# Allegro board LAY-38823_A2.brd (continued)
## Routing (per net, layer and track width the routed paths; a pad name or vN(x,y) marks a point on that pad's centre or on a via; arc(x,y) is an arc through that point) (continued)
VDD_ARM_0V9: length 27
  TOP w0.203: v2(14.96,14.43) 15.24,14.43 15.69,14.88 R191.2
  TOP w0.254: U1.W16 24.49,26.29 v1(24.45,26.25) ; v1(24.97,27.21) U1.V16
  L3_IN1 w0.104: v1(23.5,27.76) 22.01,27.76 20.65,26.39 19.53,26.39 18.92,25.78 18.92,18.39 v2(14.96,14.43)
  BOTTOM w0.254: v1(23.5,27.76) 23.49,27.75 v1(23.49,27.2) ; v1(23.49,27.2) 23.49,26.95 22.99,26.45 C251.1 ; v1(23.49,27.2) 23.64,27.06 C33.1 ; C33.1 24.46,27.06 24.61,27.21 v1(24.97,27.21) 24.94,27.18 C248.1 ; C33.1 24.45,26.82 v1(24.45,26.25) 24.33,26.37 C36.1 ; C35.1 23.38,28.5 v1(23.52,28.64) 23.67,28.49 C253.1
  vias: v1(14.73,17.65) v1(14.78,18.26) v1(15.52,18.26) v1(15.53,17.66) v1(16.17,18.27) v1(16.18,17.58)
VDD_PHY_1V2: length 64.1
  TOP w0.203: U8.1 6.31,13.34 5.88,13.78 v2(5.88,13.79) 5.77,13.89 5.64,13.89 4.47,15.06 3.53,15.06 TP31.1
  TOP w0.254: U1.J15 24.46,32.17 v1(24.47,32.17)
  L5_PWR_2 w0.381: v2(5.88,13.79) 5.93,13.84 25.44,13.84 30.28,18.68 30.28,21.49 31.75,22.96 31.75,30.51 30.27,31.99 30.27,35.22 27.68,37.81 v1(27.68,38.73)
  BOTTOM w0.254: C351.1 5.79,13.88 v2(5.88,13.79)
  BOTTOM w0.305: 25.95,32.51 25.57,32.13 C244.1 24.52,32.13 v1(24.47,32.17)
  BOTTOM w0.381: v1(27.68,38.73) 25.95,37 25.95,32.51
VDD_SNVS_0V8: length 75.8
  TOP w0.203: U8.2 6.09,12.94 5.77,13.26 5.56,13.26 v2(5.5,13.31) 4.15,14.67 TP29.1
  TOP w0.254: v1(27.48,30.73) 27.49,30.74 U1.K22 ; v2(35.01,42.77) R113.1
  L3_IN1 w0.254: v2(35.01,42.77) 35.01,40.84 35.71,40.14 36.83,40.14 38.78,38.19 38.78,37.13 36.7,35.05 36.7,32.7 35.03,31.03 30.29,31.03 29.9,31.42 28.06,31.42 27.48,30.85 v1(27.48,30.73)
  L5_PWR_2 w0.381: v2(5.5,13.31) 5.33,13.49 5.33,14.07 5.61,14.35 12.28,14.35 12.91,14.97 16.6,14.97 17.22,14.35 24.85,14.35 28.34,17.85 28.34,21.56 30.93,24.15 30.93,30.03 29.71,31.25 27.75,31.25 27.48,30.99 v1(27.48,30.73)
  BOTTOM w0.254: C9.1 27.82,31.23 27.48,30.9 v1(27.48,30.73) ; C337.1 5.84,13.31 5.59,13.31 5.58,13.31 v2(5.5,13.31)
VDD_SOC&DRAM&PU_0V9: length 45.6
  TOP w0.203: R194.2 18.95,14.86 v2(18.95,14.99)
  TOP w0.254: U1.R17 24.95,28.75 v1(24.95,29.23) ; U1.L10 21.49,30.26 v1(21.46,30.22) 21.49,30.19 U1.N10 U1.P9 U1.R10 21.49,28.26 v1(21.45,28.21) 21.49,28.17 U1.U10 ; U1.P12 22.03,29.21 v1(22.03,29.21) ; 21.99,29.24 v1(22.03,29.21) ; v1(22.03,29.21) 21.99,29.17 U1.R11 ; U1.U17 U1.U18 25.53,27.75 v1(25.53,28.2) 25.53,28.67 U1.R18 25.52,28.74 v1(25.52,29.22) ; U1.U10 U1.W10 ; U1.U10 U1.U11 ; U1.L17 U1.L18 25.5,30.7 v1(25.5,30.21) 25.49,30.21 U1.N18 25.52,29.68 v1(25.52,29.22) ; v1(24.95,29.23) 24.95,29.67 U1.N17 ; v1(24.95,29.23) 24.96,29.22 v1(25.52,29.22) ; v1(24.95,29.23) 24.51,29.23 U1.P16 U1.N15 U1.M15 U1.L15 U1.K15
  L3_IN1 w0.076: v1(22.03,27.21) 21.49,26.67 21.49,26.23 20.93,25.67 20,25.67 19.56,25.22
  L3_IN1 w0.104: v2(18.95,14.99) 19.2,15.24 19.2,24.87 19.56,25.22
  BOTTOM w0.203: C74.1 21.13,29.9 v1(21.46,30.22) ; C1.1 23.19,31.47 v1(23.42,31.24) ; C61.1 21.08,28.02 21.27,28.21 v1(21.45,28.21)
  BOTTOM w0.254: v1(25.5,30.21) 25.77,30.49 C235.1 25.77,30.94 v1(25.54,31.17) 25.54,31.17 v1(25.04,31.17) 25.04,31.5 24.83,31.71 C256.1 ; v1(25.5,30.21) 25.5,29.72 C254.1 25.49,29.25 v1(25.52,29.22) ; v1(25.5,30.21) 25.82,30.21 C234.2 ; v1(25.52,29.22) 24.96,29.22 v1(24.95,29.23) 24.68,29.23 C247.1 24.15,29.76 v1(23.5,29.76) 23.42,29.67 C16.1 ; v1(25.52,29.22) 25.5,29.19 C255.1 25.5,28.24 v1(25.53,28.2) 25.53,27.77 C15.1 ; v1(23.49,30.69) 23.48,30.7 23.48,31.19 v1(23.42,31.24) 23.01,31.24 22.9,31.14 C20.1 22.09,31.14 v1(22.03,31.2) ; v1(22.03,29.21) 22.29,28.95 C54.1 ; v1(21.46,30.22) 21.46,30.32 21.25,30.52 C78.1 ; C55.1 22.18,27.06 v1(22.03,27.21) 21.61,27.21 C48.1
  BOTTOM w0.305: v1(23.42,31.24) 23.65,31.46 C65.1
  vias: v2(18.24,11.2) v2(18.29,12.22) v2(19,12.22) v2(19,11.23)
VDDA_1V8: length 37.3
  TOP w0.203: U8.54 8.21,14.8 v2(7.63,15.38) 7.25,15.76 5.43,15.76 5.23,15.96 5.23,16.66 TP32.1
  TOP w0.254: U1.H13 23.42,32.21 v1(23.47,32.26) 23.49,32.28 23.92,32.28 U1.H15 ; U1.AA14 23.47,25.73 v1(23.47,26.24) 23.5,26.21 U1.Y15 ; U1.P19 U1.N19 U1.N20 26.51,29.69 v1(26.51,29.23) 26.49,29.21 U1.P19 ; U1.P19 U1.R19 ; v1(18.49,29.18) 18.97,29.18 U1.P5
  L3_IN1 w0.254: 22.7,28.77 18.87,28.77 18.54,29.11 18.54,29.13 v1(18.49,29.18)
  L3_IN1 w0.381: v2(7.63,15.38) 7.63,15.26 9.04,13.84 19.38,13.84 v2(20.45,14.91)
  BOTTOM w0.203: v1(18.49,29.18) 18.44,29.13 18.39,29.13 18.33,29.07 C267.1
  BOTTOM w0.254: 24.01,22.77 23.95,22.83 23.95,24.43 23.6,24.77 23.53,24.77 23.4,24.9 C99.1 23.4,25.51 23.47,25.58 v1(23.47,26.24) ; C104.1 26.8,28.94 v1(26.51,29.23) 26.13,28.86 C101.1 ; v1(23.47,32.26) 23.47,32.5 C100.1 ; C363.1 7.63,14.91 v2(7.63,15.38)
VIN_LDO_CAP: length 0.7
  BOTTOM w0.254: v2(53.43,34.59) 53.29,34.46 C122.1
VINT: length 1.7
  TOP w0.203: C274.2 5.1,12.52 5.43,12.19 6.02,12.19 6.07,12.14 U8.4
32K_CLKIN: length 1.8
  TOP w0.104: v2(54.64,32.86) 54.49,33.02 U9.24
  BOTTOM w0.104: R115.2 v2(54.64,32.86)
ANT_IN0: length 4.5
  TOP w0.279: U9.2 67.24,25.82 arc(67.56,25.75) 67.84,25.57 67.91,25.5 arc(68.04,25.3) 68.08,25.07 68.1,25.06 C456.1 68.1,24.12 C455.1
BOOT_MODE0: length 28.9
  TOP w0.076: U1.G26 29.75,32.96 30.37,32.96
  TOP w0.104: v1(34.77,32.67) 34.58,32.48 34.03,32.48 33.53,32.98 30.38,32.98
  TOP w0.114: 30.38,32.98 30.37,32.96
  BOTTOM w0.104: R47.1 34.77,32.36 v1(34.77,32.67) 34.77,33.37 37.48,36.08 37.48,47.94 36.27,49.15 34.82,49.15 34.39,48.72 33.25,48.72 32.87,49.11 J4.98
BOOT_MODE1: length 29.5
  TOP w0.104: 30.03,32.74 33.42,32.74 33.93,32.24 35.03,32.24 35.28,32.49 v1(35.28,33.32)
  TOP w0.114: 30.03,32.74 U1.G27
  BOTTOM w0.104: J4.100 33.27,49.14 33.45,48.95 34.25,48.95 34.75,49.46 36.35,49.46 37.74,48.06 37.74,35.79 v1(35.28,33.32) 35.28,32.17 R79.1
BOOT_MODE2: length 28.7
  TOP w0.104: v1(33.81,34.8) 32.76,35.84 31.42,35.84 30.29,34.71 U1.C27
  L3_IN1 w0.081: v1(26.06,47.71) 26.89,46.88 27.12,46.88 27.54,46.46 28.17,46.46 28.45,46.19 28.45,45.16 29.54,44.07 32.47,44.07 33.64,42.89 33.64,34.96 v1(33.81,34.8)
  BOTTOM w0.104: R78.1 32.6,31.85 33.63,32.88 33.63,33.96 33.81,34.14 v1(33.81,34.8) ; J4.60 25.27,48.82 25.32,48.77 25.32,48.29 25.9,47.71 v1(26.06,47.71)
BOOT_MODE3: length 29.1
  TOP w0.076: U1.D26 29.75,34.46 30.31,34.46 31.3,35.46 31.63,35.46
  TOP w0.104: v1(24.47,48.78) 24.9,49.21 30.7,49.21 v1(35,44.91) ; 31.63,35.46 32.01,35.46 32.11,35.36 v1(32.18,35.36)
  BOTTOM w0.104: R77.1 35.96,45.86 v1(35,44.91) 34.16,44.07 34.16,37.02 32.5,35.36 v1(32.18,35.36) ; J4.56 v1(24.47,48.78)
BT_CTS_RES: length 138.6
  TOP w0.104: U9.44 v2(63.72,24.74)
  L3_IN1 w0.081: v1(8.2,40.4) 8.04,40.56 5.6,40.56 1.88,36.84 1.88,35.38 1.18,34.68 1.18,20.18 1.76,19.6 1.76,5.48 5.49,1.74 19.95,1.74 21.62,3.41 37.56,3.41 39.37,5.22 39.37,8.97 48.06,17.67 48.06,21.42 49.59,22.95 50.67,22.95 51.77,24.06 59.27,24.06 60.47,25.26 63.19,25.26 63.71,24.74 v2(63.72,24.74)
  BOTTOM w0.104: v1(8.2,40.4) 8.68,40.87 9.55,40.87 10.52,41.84 21.45,41.84 25.27,38.02 R205.1
BT_RTS_RES: length 135.3
  TOP w0.104: v2(61.02,24.72) U9.41
  L3_IN1 w0.081: v1(8.97,40.49) 8.69,40.77 5.52,40.77 1.67,36.92 1.67,35.43 0.97,34.73 0.97,20.09 1.55,19.51 1.55,5.34 5.35,1.54 20.15,1.54 21.16,2.54 21.9,2.54 22.56,3.21 37.75,3.21 39.64,5.09 39.64,8.9 48.36,17.63 48.36,21.43 49.68,22.74 50.82,22.74 51.91,23.84 60.14,23.84 v2(61.02,24.72)
  BOTTOM w0.104: v1(8.97,40.49) 9.6,40.49 10.64,41.53 21.23,41.53 24.22,38.54 R208.1
BT_RXD_RES: length 136.4
  TOP w0.104: U9.43 v2(62.82,24.73)
  L3_IN1 w0.081: v2(62.82,24.73) 61.45,23.36 52.28,23.36 51.25,22.33 49.87,22.33 48.94,21.39 48.94,17.59 40.17,8.82 40.17,5.03 37.91,2.78 28.25,2.78 26.58,1.11 5.16,1.11 1.13,5.14 1.13,19.34 0.55,19.92 0.55,20.09 0.55,36.4 1.91,37.75 1.91,37.75 5.34,41.18 9.87,41.18 10.67,40.39 v1(10.95,40.39)
  BOTTOM w0.104: R206.1 22.1,38.76 20.08,40.77 11.33,40.77 v1(10.95,40.39)
BT_TXD_RES: length 136.1
  TOP w0.104: U9.42 v2(61.92,24.72)
  L3_IN1 w0.081: v2(61.92,24.72) 60.78,23.57 52.08,23.57 51.04,22.54 49.79,22.54 48.68,21.43 48.68,17.63 39.9,8.85 39.9,5.06 37.82,2.98 28.16,2.98 26.49,1.32 5.25,1.32 1.34,5.22 1.34,19.43 0.76,20.01 0.76,36.31 1.7,37.25 5.43,40.97 9.43,40.97 v1(10.09,40.31)
  BOTTOM w0.104: v1(10.09,40.31) 10.09,40.39 10.77,41.07 21.03,41.07 23.16,38.94 R207.1
BT_WAKE_DEV: length 51
  TOP w0.076: U1.U26 29.75,27.46 30.27,27.46
  TOP w0.104: 30.27,27.46 33.63,27.46 34.15,26.93 40.53,26.93 43.59,29.99 47.54,29.99 49.75,32.2 49.75,37.77 51.34,39.37 58.57,39.37 v2(59.39,38.55) ; U9.6 v2(63.89,29.42)
  BOTTOM w0.104: v2(63.89,29.42) 63.89,30.38 59.39,34.88 v2(59.39,38.55)
BT_WAKE_HOST: length 48.3
  TOP w0.076: 31.63,26.71 U1.W27
  TOP w0.104: U9.7 62.9,30.32 v2(62.83,30.39) ; v2(57.14,38.18) 56.65,38.67 52,38.67 51.12,37.79 51.12,32.08 47.37,28.34 43.9,28.34 41.8,26.24 33.87,26.24 33.39,26.71 31.63,26.71
  BOTTOM w0.104: v2(57.14,38.18) 57.14,36.07 v2(62.83,30.39)
CLK_32K_OUT: length 77.2
  TOP w0.104: U8.7 5.3,10.94 v2(5.21,10.85) ; v2(18.5,6.18) 18.78,6.18 19.96,7.37 23.85,7.37 24.41,7.92 28.07,7.92 30.66,5.33 30.66,4.95 30.83,4.77 30.83,4.49 31.46,3.86 35.96,3.86 38.22,6.12 38.22,16.78 v2(38.51,17.06) ; v2(38.15,40.62) 37.81,40.95 R100.1
  L3_IN1 w0.081: v2(5.21,10.85) 5.21,10.31 7.47,8.05 7.97,8.05 10.52,5.5 17.82,5.5 v2(18.5,6.18)
  BOTTOM w0.104: v2(38.51,17.06) 38.28,17.29 38.28,34.75 39.06,35.53 39.06,39.71 v2(38.15,40.62)
CLKIN1: length 27.6
  TOP w0.104: v1(32.27,48.57) 32.27,48.43 36.87,43.82 TP20.1 38.56,41.56 38.56,40.05 37.67,39.17 37.67,35.7 36.25,34.28 36.25,32.65 35.95,32.35 35.53,32.35 35.18,32 33.83,32 33.32,32.5 31.7,32.5 31.13,31.93
  TOP w0.114: U1.H27 30.04,32.16 30.26,32.16 30.49,31.93 31.13,31.93
  BOTTOM w0.104: v1(32.27,48.57) 32.27,48.92 32.07,49.12 J4.94
CLKIN2: length 28.2
  TOP w0.104: v1(32.84,48.57) 32.84,48.24 38.81,42.27 38.81,39.98 37.9,39.07 37.9,35.61 36.48,34.19 36.48,32.57 36.48,32.57 36.48,32.55 36.14,32.21 36.14,31.72 35.87,31.45 33.22,31.45 TP21.1 32.26,31.45 30.25,31.45
  TOP w0.114: U1.J27 30.25,31.45
  BOTTOM w0.104: v1(32.84,48.57) 32.84,48.67 32.47,49.04 J4.96
CLKOUT1: length 28
  TOP w0.076: 30.23,32.46 29.74,32.46 U1.H26
  TOP w0.114: 30.23,32.46 30.99,32.46 v1(31.06,32.38)
  L3_IN1 w0.081: v1(31.06,32.38) 31.66,32.98 33.72,32.98 34.61,33.86 34.61,34.9 34.29,35.22 34.29,45.34 33.12,46.51 31.14,46.51 30.74,46.92 28.01,46.92 27.66,47.26 27.33,47.26 26.46,48.13 26.46,48.46 v1(26.1,48.82)
  BOTTOM w0.104: J4.64 26.07,48.85 v1(26.1,48.82)
CLKOUT2: length 28.4
  TOP w0.076: U1.J26 29.75,31.96 30.18,31.96
  TOP w0.114: v1(31.86,32.12) 31.58,32.12 31.16,31.69 30.45,31.69 30.18,31.96
  L3_IN1 w0.081: v1(26.83,48.28) 26.83,48.18 27.51,47.5 27.81,47.5 28.15,47.17 30.79,47.17 31.23,46.72 33.2,46.72 34.55,45.38 34.55,35.49 34.82,35.22 34.82,33.78 33.81,32.77 32.51,32.77 v1(31.86,32.12)
  BOTTOM w0.104: J4.66 26.47,49.07 26.48,49.05 26.48,48.66 26.83,48.32 v1(26.83,48.28)
CSI_CKN: length 13.5
  TOP w0.076: v1(22.07,45.56) 21.78,45.56 21.45,45.23 21.45,43.68 24.51,40.62 24.51,35.73 U1.A16
  BOTTOM w0.076: J4.45 22.47,46.44 22.64,46.27 22.64,45.57 22.51,45.44 22.19,45.44 v1(22.07,45.56)
CSI_CKP: length 13.6
  TOP w0.076: U1.B16 24.74,35.46 24.74,40.71 23.46,42 21.68,43.78 21.68,44.64 22.06,45.02 v1(22.07,45.02)
  BOTTOM w0.076: v1(22.07,45.02) 22.26,45.21 22.61,45.21 22.87,45.47 J4.47
CSI_DN0: length 14.3
  TOP w0.076: U1.A14 23.51,35.73 23.51,39.57 18.83,44.25 18.83,45.2 19.2,45.56 v1(19.51,45.56)
  BOTTOM w0.076: v1(19.51,45.56) 19.51,45.48 19.63,45.35 19.85,45.35 20.17,45.68 20.17,46.33 20.07,46.43 J4.33
CSI_DN1: length 14
  TOP w0.076: v1(20.78,45.55) 20.44,45.55 20.15,45.26 20.15,43.99 24.01,40.14 24.01,35.73 U1.A15
  BOTTOM w0.076: J4.39 21.27,46.4 21.44,46.23 21.44,45.63 21.15,45.34 20.98,45.34 v1(20.78,45.55)
CSI_DN2: length 13.3
  TOP w0.076: v1(23.26,45.56) 22.99,45.56 22.64,45.21 22.64,43.43 25.01,41.06 25.01,35.73 U1.A17
  BOTTOM w0.076: v1(23.26,45.56) 23.49,45.34 23.73,45.34 23.81,45.41 23.81,46.34 23.67,46.48 J4.51
CSI_DN3: length 12.9
  TOP w0.076: v1(24.51,45.56) 24.23,45.56 23.89,45.22 23.89,43.29 25.52,41.66 25.52,35.73 U1.A18
  BOTTOM w0.076: J4.57 24.87,46.47 25,46.33 25,45.43 24.93,45.35 24.72,45.35 v1(24.51,45.56)
CSI_DP0: length 14.4
  TOP w0.076: v1(19.48,45.02) 19.46,45.02 19.06,44.62 19.06,44.34 23.74,39.66 23.74,35.46 U1.B14
  BOTTOM w0.076: v1(19.48,45.02) 19.59,45.12 19.94,45.12 20.41,45.59 20.41,46.37 20.47,46.43 J4.35
CSI_DP1: length 14
  TOP w0.076: v1(20.78,45.02) 20.38,44.62 20.38,44.09 24.24,40.23 24.24,35.46 U1.B15
  BOTTOM w0.076: J4.41 21.67,45.53 21.25,45.11 20.87,45.11 v1(20.78,45.02)
CSI_DP2: length 13.4
  TOP w0.076: v1(23.29,45.03) 22.87,44.61 22.87,43.52 25.24,41.15 25.24,35.46 U1.B17
  BOTTOM w0.076: v1(23.29,45.03) 23.37,45.11 23.83,45.11 24.04,45.32 24.04,46.23 24.07,46.26 J4.53
CSI_DP3: length 13
  TOP w0.076: v1(24.51,45.03) 24.51,45.01 24.12,44.62 24.12,43.39 25.75,41.76 25.75,35.46 U1.B18
  BOTTOM w0.076: v1(24.51,45.03) 24.61,45.12 25.02,45.12 25.23,45.33 25.23,46.21 25.27,46.25 J4.59
DRAM_CA0_A: length 19
  TOP w0.084: U1.J6 19.31,31.9 19.31,31.95 v1(19.1,32.16)
  TOP w0.089: v1(2.98,31.11) 2.95,31.11 U2.H2
  L3_IN1 w0.081: v1(19.1,32.16) 19.1,32.13 18.49,31.52 15.95,31.52 15.03,32.44 10.82,32.44 10.29,32.97 8.89,32.97 8.02,32.1 7.36,32.1 7.07,31.81 4.45,31.81 3.99,31.34 3.15,31.34 2.98,31.18 v1(2.98,31.11)
DRAM_CA1_A: length 20.5
  TOP w0.084: v1(19,30.76) 19.04,30.76 U1.K6
  TOP w0.089: v1(2.99,30.48) 2.94,30.48 U2.J2
  L3_IN1 w0.081: v1(19,30.76) 19,30.81 18.54,31.27 15.62,31.27 15.06,31.83 13.89,31.83 13.78,31.71 13.78,31.6 13.7,31.52 13.54,31.52 13.46,31.6 13.46,31.71 13.37,31.8 13.21,31.8 13.13,31.71 13.13,31.6 13.05,31.52 12.89,31.52 12.81,31.6 12.81,31.71 12.72,31.8 12.56,31.8 12.48,31.71 12.48,31.6 12.4,31.52 12.24,31.52 12.15,31.6 12.15,31.71 12.07,31.8 10.75,31.8 9.82,32.72 9.15,32.72 8.15,31.72 8.15,31.57 7.62,31.04 5.2,31.04 4.82,31.42 4.44,31.42 4.04,31.01 3.53,31.01 v1(2.99,30.48)
DRAM_CA2_A: length 16.6
  TOP w0.084: U2.H9 7.94,31.72 v1(7.8,31.72) ; U1.E4 18.49,34.15 v1(18.53,34.18)
  BOTTOM w0.104: v1(18.53,34.18) 18.48,34.18 17.22,32.92 17.22,32.23 16.58,31.6 14.68,31.6 14.43,31.85 14.43,32.38 14.32,32.49 13.61,32.49 13.51,32.38 13.51,31.88 13.43,31.8 13.04,31.8 12.94,31.9 12.94,32.34 12.83,32.45 12.62,32.45 12.52,32.34 12.52,31.9 12.42,31.8 12.21,31.8 12.1,31.9 12.1,32.34 12,32.45 10.88,32.45 10.51,32.82 9.22,32.82 8.13,31.72 v1(7.8,31.72)
DRAM_CA3_A: length 15.7
  TOP w0.084: v1(9.38,31.16) 9.31,31.16 U2.H10 ; v1(18.96,33.76) 18.99,33.79 U1.D5
  BOTTOM w0.104: v1(9.38,31.16) 9.65,31.16 9.75,31.06 9.75,30.15 10.13,29.77 12.01,29.77 12.11,29.87 12.11,30.52 12.29,30.69 12.54,30.69 12.66,30.57 12.66,29.95 12.76,29.84 12.97,29.84 13.08,29.95 13.08,30.71 13.18,30.81 16.3,30.81 17.5,32 17.5,32.77 18.49,33.76 v1(18.96,33.76)
DRAM_CA4_A: length 10.5
  TOP w0.081: U2.H11 10.17,31.1 v1(10.17,31.06)
  TOP w0.084: v1(18.43,30.17) 18.49,30.12 18.49,29.71 U1.N4
  L3_IN1 w0.081: v1(18.43,30.17) 18.41,30.17 17.93,29.69 11,29.69 10.54,30.15 10.54,30.76 10.23,31.06 v1(10.17,31.06)
DRAM_CA5_A: length 10.8
  TOP w0.076: U1.N5 18.99,30.12 v1(18.94,30.17)
  TOP w0.081: U2.J11 10.11,30.51 v1(10.18,30.51)
  L3_IN1 w0.081: 10.81,29.42 17.9,29.42 18.24,29.76 18.59,29.76 18.94,30.12 v1(18.94,30.17)
  L3_IN1 w0.084: 10.81,29.42 10.18,30.05 v1(10.18,30.51)
DRAM_CK_C_A: length 13.8
  TOP w0.076: v1(16.05,30.2) 16.05,30.44 16.13,30.52 16.62,30.52 16.77,30.66 16.94,30.66 U1.L1
  TOP w0.084: U2.J9 7.89,30.55 7.88,30.55 7.8,30.46 v1(7.8,30.45)
  BOTTOM w0.107: v1(16.05,30.2) 16.21,30.04 16.21,29.89 15.35,29.03 8.09,29.03 7.27,29.85 7.27,30.37 7.49,30.59 7.66,30.59 v1(7.8,30.45) 8.12,30.78 R8.2
DRAM_CK_T_A: length 13.9
  TOP w0.076: U1.L2 17.34,30.71 17.1,30.46 16.85,30.46 v1(16.56,30.17)
  TOP w0.084: v1(6.96,30.48) 7.03,30.48 U2.J8
  BOTTOM w0.107: R8.1 6.96,30.7 v1(6.96,30.48) 7.04,30.39 7.04,29.76 8,28.8 15.44,28.8 16.56,29.92 v1(16.56,30.17)
DRAM_CKE0_A: length 19.3
  TOP w0.076: 18.49,33.03 18.49,32.88 v1(18.61,32.77)
  TOP w0.084: v1(6.88,33.07) 6.37,32.56 6.37,30.88 5.39,29.89 4.86,29.89 4.6,30.16 4.6,30.42 U2.J4 ; U1.F4 18.49,33.03
  L3_IN1 w0.081: v1(6.88,33.07) 7.82,34.01 9.9,34.01 10.1,33.81 17.56,33.81 v1(18.61,32.77)
  BOTTOM w0.084: v1(6.88,33.07) 6.69,32.88 R121.2
DRAM_CKE1_A: length 20.2
  TOP w0.076: v1(19.2,32.77) 18.99,32.98 18.99,33.08
  TOP w0.084: 18.99,33.08 18.99,33.2 U1.F5
  TOP w0.089: U2.J5 v1(5.43,30.39)
  L3_IN1 w0.081: v1(19.2,32.77) 19.35,32.77 19.47,32.65 19.47,30.64 19.3,30.48 19.3,29.97 18.9,29.56 18.32,29.56 17.48,28.73 6.52,28.73 5.43,29.83 v1(5.43,30.39)
  BOTTOM w0.084: v1(5.43,30.39) 5.43,30.39 R158.2
DRAM_DMI0: length 19.7
  TOP w0.081: 18.49,35.81 18.49,36.14 18.28,36.35 18.28,36.75 18.28,36.75
  TOP w0.084: 17.91,37.36 18.28,36.98 18.28,36.75 ; U2.C3 3.71,35.06 v1(3.78,35.06) ; U1.A4 18.49,35.81
  TOP w0.104: 17.91,37.36 17.91,37.66 17.67,37.91 17.03,37.91 v1(16.61,37.49)
  L3_IN1 w0.081: v1(16.61,37.49) 16.61,37.49 15.84,36.71 13.65,36.71 12.11,38.25 6.53,38.25 4.14,35.86 4.14,35.42 v1(3.78,35.06)
DRAM_DMI1: length 9.7
  TOP w0.076: 16.41,33.34 16.55,33.21 U1.F1
  TOP w0.104: 16.41,33.34 15.33,33.34 15.23,33.24 14.11,33.24 11.62,35.72 10.38,35.72 10.14,35.49 10.14,35.31 9.9,35.07 9.32,35.07 U2.C10
DRAM_DQ00: length 20.3
  TOP w0.081: v1(18.35,37.46) 18.35,37.37 19.07,36.66
  TOP w0.084: U1.A5 19.07,35.79 19.07,36.66 ; v1(2.94,35.74) 2.94,35.74 U2.B2
  L3_IN1 w0.081: v1(18.35,37.46) 18.32,37.46 16.54,39.24 6.2,39.24 2.92,35.96 2.92,35.76 v1(2.94,35.74)
DRAM_DQ01: length 20.5
  TOP w0.076: U1.B5 18.74,35.46 18.74,35.8
  TOP w0.081: v1(18.67,36.54) 18.74,36.47 18.74,35.81 18.74,35.8
  TOP w0.084: v1(2.91,35.08) 2.91,35.06 U2.C2
  L3_IN1 w0.081: v1(18.67,36.54) 17.79,37.42 17.79,37.45 16.3,38.94 14.46,38.94 14.23,38.71 6.29,38.71 3.33,35.75 3.33,35.49 v1(2.91,35.08)
DRAM_DQ02: length 18.2
  TOP w0.076: v1(15.67,35.33) 15.85,35.33 16.1,35.08 16.1,34.77 16.42,34.46 17.25,34.46
  TOP w0.084: U2.E2 2.9,33.76 v1(2.94,33.76) ; U1.D2 17.25,34.46
  L3_IN1 w0.081: v1(15.67,35.33) 15.13,34.8 12.04,34.8 11.4,35.43 7.51,35.43 7.1,35.02 6.64,35.02 5.99,34.37 5.99,33.6 5.56,33.17 5.26,33.17 4.8,32.72 4.49,32.72 3.78,33.43 3.27,33.43 v1(2.94,33.76)
DRAM_DQ03: length 16.9
  TOP w0.084: v1(15.67,34.82) 15.74,34.75 15.9,34.75 16.44,34.21 U1.D1 ; v1(3.02,33.16) 2.96,33.16 U2.F2
  L3_IN1 w0.076: 15.6,34.76 15.31,34.47 15.22,34.47
  L3_IN1 w0.081: 15.22,34.47 11.69,34.47 11.4,34.76 7.66,34.76 7.42,34.51 6.7,34.51 6.5,34.31 6.5,33.4 5.57,32.46 4.26,32.46 3.56,33.16 v1(3.02,33.16) ; 15.6,34.76 v1(15.67,34.82)
DRAM_DQ04: length 15.8
  TOP w0.076: v1(16.53,34.86) 16.59,34.86 16.74,34.71 U1.C1
  TOP w0.084: U2.F4 4.33,32.78 v1(4.62,33.08)
  L3_IN1 w0.081: v1(4.62,33.08) 5.09,33.54 5.09,34.26 5.3,34.46 5.45,34.46 6.73,35.74 7.06,35.74 7.62,36.3 11.28,36.3 12.33,35.24 15,35.24 15.47,35.7 15.88,35.7 16.13,35.45 16.13,35.26 v1(16.53,34.86)
DRAM_DQ05: length 16.2
  TOP w0.076: U1.B1 16.92,35.28 16.57,35.28 16.41,35.44 16.41,35.58 v1(16.55,35.72)
  TOP w0.084: U2.E4 4.51,33.76 v1(4.58,33.76)
  L3_IN1 w0.081: v1(4.58,33.76) 4.88,34.05 4.88,34.8 5.1,35.03 5.7,35.03 6.5,35.83 6.5,36.35 6.96,36.8 11.5,36.8 12.7,35.61 15.01,35.61 15.29,35.89 16.38,35.89 v1(16.55,35.72)
DRAM_DQ06: length 16
  TOP w0.081: U1.A3 17.99,35.86 v1(17.76,36.1)
  TOP w0.084: U2.C4 4.52,35.07 4.54,35.07 v1(4.57,35.1)
  L3_IN1 w0.081: v1(4.57,35.1) 5.21,35.74 5.77,35.74 6.04,36.01 6.04,36.49 6.83,37.29 11.66,37.29 13,35.94 14.96,35.94 15.11,36.1 v1(17.76,36.1)
DRAM_DQ07: length 18.5
  TOP w0.076: 18.24,35.98 18.24,35.62 18.25,35.61
  TOP w0.081: 18.24,36.16 18.12,36.28 18.12,36.87 17.88,37.11 17.64,37.11 v1(17.42,37.33)
  TOP w0.084: v1(4.53,35.73) 4.41,35.73 4.18,35.5 U2.B4 ; 18.25,35.61 18.25,35.6 18.49,35.36 U1.B4 ; 18.24,36.16 18.24,35.98
  L3_IN1 w0.081: v1(17.42,37.33) 17.35,37.26 17.35,36.47 17.18,36.3 13.35,36.3 11.91,37.74 6.54,37.74 v1(4.53,35.73)
DRAM_DQ08: length 9.6
  TOP w0.076: U1.F2 17.24,33.46 16.55,33.46 16.46,33.55 15.22,33.55
  TOP w0.104: U2.B11 9.78,35.61 10.19,36.01 10.19,36.06 10.46,36.33 11.8,36.33 14.58,33.55 15.22,33.55
DRAM_DQ09: length 9.1
  TOP w0.076: U1.G2 17.49,32.83 17.36,32.96 16.59,32.96 16.51,33.05 16.49,33.05 16.38,33.16 15.63,33.16
  TOP w0.104: U2.C11 9.79,34.73 9.94,34.73 10.29,35.08 11.39,35.08 13.55,32.93 15.4,32.93 15.63,33.16
DRAM_DQ10: length 9.7
  TOP w0.076: U1.J1 16.91,31.71 16.76,31.56 15.88,31.56
  TOP w0.084: 11.22,33.13 10.75,33.13 10.72,33.11
  TOP w0.104: 15.88,31.56 15.44,32 12.62,32 11.49,33.13 11.22,33.13 ; U2.E9 8.51,33.11 10.72,33.11
DRAM_DQ11: length 8.9
  TOP w0.076: 15.47,32.44 16.18,31.72 16.66,31.72 16.89,31.96 17.25,31.96 U1.J2
  TOP w0.084: U2.E11 10.13,33.78 11.33,33.78
  TOP w0.104: 15.47,32.44 12.9,32.44 11.56,33.78 11.33,33.78
DRAM_DQ12: length 8.5
  TOP w0.076: 17.39,31.46 16.89,31.46 16.81,31.38
  TOP w0.084: 16.12,31.38 16.81,31.38 ; 10.63,32.44 11.31,32.44
  TOP w0.104: U2.F11 10.11,32.46 10.6,32.46 10.63,32.44 ; 17.39,31.46 17.49,31.35 U1.K2 ; 11.31,32.44 11.5,32.44 12.56,31.38 16.12,31.38
DRAM_DQ13: length 12.2
  TOP w0.076: 15.95,30.96 16.2,31.21 U1.K1
  TOP w0.084: 15.7,30.96 15.95,30.96
  TOP w0.104: U2.F9 8.53,32.44 8.53,30.22 9.21,29.53 11.09,29.53 12.52,30.96 15.7,30.96
DRAM_DQ14: length 11.5
  TOP w0.076: U1.E1 16.71,33.71 16.67,33.75 15.33,33.75
  TOP w0.084: U2.B9 7.89,35.67 7.89,36.15 8.44,36.7
  TOP w0.104: 8.44,36.7 12.38,36.7 15.33,33.75
DRAM_DQ15: length 13.3
  TOP w0.076: U1.E2 17.25,33.96 15.9,33.96
  TOP w0.104: 15.9,33.96 12.77,37.08 8.49,37.08 7.68,36.28 7.68,35.23 U2.C9
DRAM_NCS0_A: length 20.2
  TOP w0.084: U2.H4 4.18,31.45 v1(4.58,31.05) ; U1.K4 18.37,31.21 18.29,31.13 18.29,30.88 v1(18.46,30.71)
  L3_IN1 w0.081: v1(4.58,31.05) 4.8,30.83 8.18,30.83 8.84,31.5 10.41,31.5 10.84,31.06 12.13,31.06 12.32,30.88 12.32,30.74 12.4,30.66 12.56,30.66 12.64,30.74 12.64,30.88 12.72,30.96 12.89,30.96 12.97,30.88 12.97,30.74 13.05,30.66 13.21,30.66 13.29,30.74 13.29,30.88 13.37,30.96 13.54,30.96 13.62,30.88 13.62,30.74 13.7,30.66 13.86,30.66 13.94,30.74 13.94,30.88 14.02,30.96 14.19,30.96 14.27,30.88 14.27,30.74 14.35,30.66 14.51,30.66 14.59,30.74 14.59,30.88 14.67,30.96 14.84,30.96 14.92,30.88 14.92,30.74 15,30.66 15.16,30.66 15.24,30.74 15.24,30.88 15.32,30.96 15.49,30.96 15.57,30.88 15.57,30.74 15.65,30.66 15.81,30.66 15.89,30.74 15.89,30.88 15.97,30.96 17,30.96 17.08,30.88 17.08,30.18 17.16,30.1 17.41,30.1 17.49,30.18 17.49,30.97 17.57,31.05 18.38,31.05 18.46,30.97 v1(18.46,30.71)
DRAM_NCS1_A: length 18.9
  TOP w0.084: U2.H3 3.38,31.6 3.61,31.83 v1(3.73,31.83) ; v1(18.59,32.13) 18.49,32.03 U1.J4
  L3_IN1 w0.081: v1(3.73,31.83) 4.02,31.83 4.32,32.13 5.89,32.13 6.37,32.61 7.18,32.61 7.42,32.84 8.07,32.84 8.53,33.3 10.69,33.3 10.85,33.14 14.76,33.14 16.16,31.73 16.65,31.73 16.76,31.85 16.76,32.39 16.84,32.47 17.01,32.47 17.09,32.39 17.09,32.18 17.17,32.1 17.32,32.1 17.4,32.19 17.4,32.38 17.48,32.46 17.65,32.46 17.73,32.38 17.73,31.95 17.81,31.86 18.33,31.86 18.41,31.95 18.41,31.95 v1(18.59,32.13)
DRAM_NRESET: length 9.1
  TOP w0.084: U2.T11 10.12,26.62 11.53,26.62
  TOP w0.104: 11.53,26.62 11.76,26.62 11.99,26.4 R204.2 14.81,26.4 v1(16.41,27.99) 16.41,28.12 U1.R1
  BOTTOM w0.104: v1(16.41,27.99) 16.71,28.29 R4.2
DRAM_SDQS0_C: length 17.2
  TOP w0.076: U1.B2 17.49,35.3 17.24,35.55
  TOP w0.081: 16.77,36.32 17.24,35.85 17.24,35.77 17.24,35.76 17.24,35.55
  TOP w0.084: v1(3.77,33.82) U2.E3
  TOP w0.089: v1(16.43,36.67) 16.77,36.32
  BOTTOM w0.081: 4.77,34.09 4.11,34.09
  BOTTOM w0.107: 4.11,34.09 3.84,33.82 v1(3.77,33.82) ; 4.77,34.09 5.26,34.57 5.26,34.58 5.45,34.77 7.08,34.77 7.74,35.43 7.74,36.35 8.35,36.96 13.05,36.96 13.54,36.47 16.02,36.47 16.22,36.67 v1(16.43,36.67)
DRAM_SDQS0_T: length 17.1
  TOP w0.081: U1.A2 17.49,35.87 17.45,35.92 17.45,35.94 16.98,36.4 v1(16.98,36.69)
  TOP w0.084: v1(3.78,34.41) 3.78,34.34 3.53,34.08 U2.D3
  BOTTOM w0.081: 5.1,34.74 4.12,34.74
  BOTTOM w0.107: 4.12,34.74 v1(3.78,34.41) ; v1(16.98,36.69) 16.64,37.03 16.26,37.03 16.13,36.9 16.13,36.9 15.93,36.7 13.63,36.7 13.15,37.18 8.26,37.18 7.52,36.44 7.52,35.53 6.99,35 5.35,35 5.1,34.74
DRAM_SDQS1_C: length 10.6
  TOP w0.084: v1(8.58,33.66) 8.81,33.43 U2.E10
  TOP w0.089: U1.H1 16.85,32.36 16.6,32.36 v1(16.35,32.11)
  BOTTOM w0.107: v1(16.35,32.11) 15.55,32.11 12.93,34.72 9.91,34.72 9.45,34.26 9.25,34.26 9.25,34.26 9.2,34.26 v1(8.58,33.66)
DRAM_SDQS1_T: length 10.5
  TOP w0.084: v1(8.59,34.44) 8.63,34.44 U2.D10
  TOP w0.089: v1(16.32,32.66) 16.4,32.66 16.5,32.57 16.85,32.57 U1.G1
  BOTTOM w0.107: v1(8.59,34.44) 8.65,34.49 9.03,34.49 9.35,34.49 9.82,34.95 13.03,34.95 15.64,32.34 15.99,32.34 v1(16.32,32.66)
DRAM_ZQ0: length 1.3
  TOP w0.254: U2.A5 5.54,36.03 v1(5.62,36.12)
  BOTTOM w0.305: v1(5.62,36.12) 5.45,35.95 R5.2
DRAM_ZQ1: length 1.1
  TOP w0.254: v1(6.9,36.1) 6.96,36.03 U2.A8
  BOTTOM w0.254: v1(6.9,36.1) 6.76,35.95 R157.2
DSI_CKN: length 16.1
  TOP w0.076: U1.A11 22.01,35.73 22.01,38.57 18.6,41.99 16.35,41.99 15.31,43.03 15.31,44.96 15.9,45.54 v1(16,45.54)
  BOTTOM w0.076: v1(16,45.54) 16.15,45.39 16.31,45.39 16.57,45.66 16.57,46.35 16.47,46.45 J4.15
DSI_CKP: length 16.5
  TOP w0.076: U1.B11 22.24,35.46 22.24,35.63 22.24,35.63 22.24,38.67 18.69,42.22 16.45,42.22 15.54,43.12 15.54,44.63 15.92,45 v1(15.98,45)
  BOTTOM w0.076: v1(15.98,45) 16.14,45.17 16.4,45.17 16.8,45.57 16.8,46.21 16.87,46.28 J4.17
DSI_DN0: length 17
  TOP w0.076: v1(13.82,45.51) 13.72,45.6 13.5,45.6 13.42,45.52 13.42,44.92 13.17,44.67 13.17,42.86 15.36,40.67 18.33,40.67 21.02,37.98 21.02,35.73 U1.A9
  BOTTOM w0.076: J4.3 14.07,46.31 14.24,46.13 14.24,45.73 14.01,45.51 v1(13.82,45.51)
DSI_DN1: length 16.6
  TOP w0.076: v1(14.88,45.51) 14.81,45.58 14.5,45.58 14.25,45.33 14.25,42.9 15.83,41.32 18.47,41.32 21.52,38.27 21.52,35.73 U1.A10
  BOTTOM w0.076: v1(14.88,45.51) 15.1,45.51 15.38,45.78 15.38,46.33 15.27,46.45 J4.9
DSI_DN2: length 15.5
  TOP w0.076: U1.A12 22.51,35.73 22.51,38.85 18.65,42.71 17.22,42.71 16.57,43.37 16.57,45.35 16.81,45.59 17.11,45.59 v1(17.17,45.53)
  BOTTOM w0.076: J4.21 17.67,46.47 17.77,46.37 17.77,45.74 17.42,45.39 17.31,45.39 v1(17.17,45.53)
DSI_DN3: length 14.8
  TOP w0.076: U1.A13 23.02,35.73 23.02,39.23 18.72,43.53 18.27,43.53 17.75,44.04 17.75,45.47 17.9,45.62 18.31,45.62 v1(18.38,45.56)
  BOTTOM w0.076: v1(18.38,45.56) 18.52,45.41 18.73,45.41 18.91,45.59 18.91,46.7 J4.27
DSI_DP0: length 17.1
  TOP w0.076: v1(13.79,44.96) 13.78,44.96 13.4,44.57 13.4,42.96 15.45,40.9 18.42,40.9 21.25,38.08 21.25,35.46 U1.B9
  BOTTOM w0.076: J4.5 14.47,45.64 v1(13.79,44.96)
DSI_DP1: length 16.7
  TOP w0.076: v1(14.86,44.96) 14.86,44.95 14.48,44.57 14.48,42.99 15.93,41.55 18.56,41.55 21.74,38.37 21.74,36.13 21.75,36.02 21.75,35.46 U1.B10
  BOTTOM w0.076: J4.11 15.67,46.4 15.61,46.34 15.61,45.69 14.88,44.96 v1(14.86,44.96)
DSI_DP2: length 15.6
  TOP w0.076: v1(17.17,45) 16.8,44.63 16.8,43.46 17.32,42.94 18.75,42.94 22.74,38.95 22.74,35.46 U1.B12
  BOTTOM w0.076: J4.23 18.07,46.46 18,46.39 18,45.65 17.51,45.16 17.33,45.16 v1(17.17,45)
DSI_DP3: length 14.8
  TOP w0.076: v1(18.41,45.03) 18.41,45.01 17.98,44.58 17.98,44.14 18.36,43.76 18.82,43.76 23.25,39.33 23.25,35.46 U1.B13
  BOTTOM w0.076: v1(18.41,45.03) 18.57,45.18 18.82,45.18 19.14,45.5 19.14,46.27 19.27,46.4 J4.29
ECSPI2_MISO: length 20.6
  TOP w0.084: 19.48,37.39 19.48,37.31 19.91,36.88 19.97,36.88 20.4,36.45 20.4,35.8 U1.A8
  TOP w0.104: 19.47,37.39 19.47,38.51 17.81,40.17 15,40.17 12.71,42.46 12.71,45.58 15.05,47.91 15.77,47.91 15.99,48.14 15.99,48.35 v1(16.47,48.83)
  TOP w0.114: 19.47,37.39 19.48,37.39
  BOTTOM w0.104: J4.16 16.47,48.83 v1(16.47,48.83)
ECSPI2_MOSI: length 21.2
  TOP w0.076: U1.B8 20.75,35.46 20.75,36.62 v1(20.65,36.72)
  L3_IN1 w0.081: v1(16.45,48.27) 16.11,47.93 14.98,47.93 13.39,46.34 13.39,44.26 15.84,41.82 18.19,41.82 21.03,38.98 21.03,37.09 v1(20.65,36.72)
  BOTTOM w0.104: v1(16.45,48.27) 16.87,48.68 J4.18
ECSPI2_SCLK: length 23.6
  TOP w0.076: U1.E6 19.98,33.71 v1(19.99,33.72)
  L3_IN1 w0.081: v1(15.61,48.3) 15.29,48.61 15.29,48.83 14.93,49.2 13.48,49.2 12.67,48.39 12.67,43.94 15.7,40.92 15.99,40.92 18.8,38.11 18.8,37.03 19.08,36.75 19.08,34.6 19.95,33.72 v1(19.99,33.72)
  BOTTOM w0.104: J4.14 16.07,48.69 15.68,48.3 v1(15.61,48.3)
ECSPI2_SS0: length 22.2
  TOP w0.084: U1.A6 19.25,35.95 19.25,36.73 18.75,37.23
  TOP w0.104: 18.75,37.23 18.75,38.21 17.59,39.36 14.41,39.36 11.86,41.91 11.86,47.65 13.42,49.21 15.29,49.21 v1(15.67,48.83)
  BOTTOM w0.104: J4.12 v1(15.67,48.83)
EMMC_VDDIM: length 4
  TOP w0.076: 41.26,38.09 41.79,38.09 U4.C2 41.78,37.59 41.36,37.59 v1(41.06,37.89) 41.26,38.09
  BOTTOM w0.076: 41.21,38.04 v1(41.06,37.89)
  BOTTOM w0.104: C137.1 C136.1 41.21,38.04
ENET_MDC: length 22.9
  TOP w0.076: U1.AC27 31.63,24.71
  TOP w0.104: 31.63,24.71 31.69,24.71 31.95,24.44 33.37,24.44 34.79,23.02 v1(35.09,23.02)
  L3_IN1 w0.081: v1(35.09,23.02) 35.24,23.17 35.88,23.17 37.55,24.83 45.98,24.83 47.07,25.92 49.34,25.92 v1(49.67,26.26)
  BOTTOM w0.104: J7.18 49.42,25.5 49.67,25.75 v1(49.67,26.26)
ENET_MDIO: length 21.3
  TOP w0.076: 31.63,25.21 U1.AB27
  TOP w0.104: 31.63,25.21 32.93,25.21 34.57,23.57 v1(35.74,23.57)
  L3_IN1 w0.081: v1(35.74,23.57) 35.75,23.57 35.86,23.57 37.34,25.04 45.36,25.04 46.62,26.3 v1(49.11,26.3)
  BOTTOM w0.104: J7.20 v1(49.11,26.3)
ENET_RD0: length 24.3
  TOP w0.076: 31.63,23.45 30.95,23.45 30.69,23.71 U1.AE27
  TOP w0.104: v1(37.03,21.34) 36.64,20.96 35.52,20.96 33.03,23.45 31.63,23.45
  L3_IN1 w0.081: v1(37.03,21.34) 37.48,21.34 38.77,22.63 44.36,22.63 44.85,23.12 49.47,23.12 v1(50.36,24.01)
  BOTTOM w0.104: J7.8 49.67,23.5 49.81,23.63 50.09,23.63 50.31,23.85 50.31,23.96 v1(50.36,24.01)
ENET_RD1: length 23.3
  TOP w0.076: 31.63,23.91 31.34,23.91 31.05,24.21 U1.AD27
  TOP w0.104: v1(36.7,22.61) 36.2,22.11 35.03,22.11 33.22,23.91 31.63,23.91
  L3_IN1 w0.081: v1(36.7,22.61) 36.85,22.61 38.33,24.09 45.8,24.09 47.15,25.44 48.23,25.44 49.65,24.01 v1(49.77,24.01)
  BOTTOM w0.104: v1(49.77,24.01) 49.66,23.9 J7.10
ENET_RD2: length 30.3
  TOP w0.076: 31.63,23.68 31.05,23.68 30.77,23.96 29.74,23.96 U1.AD26
  TOP w0.104: v1(35.82,21.36) 35.45,21.36 33.13,23.68 31.63,23.68
  L3_IN1 w0.081: v1(35.82,21.36) 34.84,20.38 34.84,19.59 35.33,19.1 37.84,19.1 39.39,20.65 v1(44.3,20.65)
  BOTTOM w0.104: J7.12 49.52,24.3 49.62,24.4 50.58,24.4 50.75,24.23 50.75,23.18 50.03,22.46 50.02,22.46 48.58,21.02 45.2,21.02 44.83,20.65 v1(44.3,20.65)
ENET_RD3: length 26.5
  TOP w0.076: 30.65,24.46 29.75,24.46 U1.AC26
  TOP w0.104: 30.65,24.46 31.45,24.46 31.69,24.21 33.27,24.21 34.93,22.56 v1(35.83,22.56)
  L3_IN1 w0.081: v1(35.83,22.56) 36.16,22.24 36.94,22.24 38.56,23.87 46.32,23.87 v1(47.52,25.07)
  BOTTOM w0.104: v1(47.52,25.07) 47.52,25.58 48.64,26.7 49.87,26.7 50.17,26.4 50.17,25.12 49.86,24.81 49.52,24.81 49.4,24.7 J7.14
ENET_RX_CTL: length 21.8
  TOP w0.076: 31.63,22.99 30.71,22.99 30.49,23.21 U1.AF27
  TOP w0.104: v1(37.11,20.3) 37.11,20.27 36.96,20.12 35.71,20.12 32.84,22.99 31.63,22.99
  L3_IN1 w0.081: v1(37.11,20.3) 37.76,20.3 39.32,21.86 45.74,21.86 v1(46.08,21.51)
  BOTTOM w0.104: v1(46.08,21.51) 47.33,21.51 47.68,21.86 49.01,21.86 49.11,21.97 J7.2
ENET_RXC: length 21.8
  TOP w0.076: U1.AE26 29.74,23.46 30.58,23.46 30.68,23.36
  TOP w0.104: v1(36.07,20.57) 35.58,20.57 32.93,23.22 30.82,23.22 30.68,23.36
  L3_IN1 w0.081: v1(36.07,20.57) 36.4,20.9 37.56,20.9 38.98,22.32 47.3,22.32 v2(47.53,22.56)
  BOTTOM w0.104: v2(47.53,22.56) 47.67,22.7 J7.4
ENET_TD0: length 19.1
  TOP w0.104: U1.AG26 29.5,22.71 29.97,22.24 30.12,22.24 30.22,22.13 30.56,22.13 30.96,22.53 32.51,22.53 34.1,20.94 34.1,20.86 v1(34.11,20.85)
  L3_IN1 w0.081: v1(34.11,20.85) 34.11,20.87 35.27,22.03 37.22,22.03 38.85,23.66 44.68,23.66 v1(44.84,23.49)
  BOTTOM w0.104: J7.9 45.23,23.9 44.84,23.5 v1(44.84,23.49)
ENET_TD1: length 21.2
  TOP w0.076: U1.AF26 29.74,22.96 30.52,22.96 30.72,22.76
  TOP w0.104: v1(35.8,19.7) 32.74,22.76 30.72,22.76
  L3_IN1 w0.081: v1(43.69,21.21) 39.52,21.21 37.63,19.31 36.13,19.31 35.84,19.61 35.84,19.66 v1(35.8,19.7)
  BOTTOM w0.104: J7.11 45.31,24.3 45.09,24.08 44.88,24.08 44.44,23.63 44.44,21.96 v1(43.69,21.21)
ENET_TD2: length 22
  TOP w0.104: U1.AG25 28.99,22.44 29.3,22.13 29.55,22.13 30.48,21.2 30.48,20.75 31.5,19.73 33.74,19.73 v1(34.26,20.26)
  L3_IN1 w0.081: v1(44.9,24.46) 37.53,24.46 36,22.93 35.64,22.93 33.73,21.02 33.73,20.71 34.18,20.26 v1(34.26,20.26)
  BOTTOM w0.104: J7.13 45.14,24.7 44.97,24.52 44.96,24.52 v1(44.9,24.46)
ENET_TD3: length 22.8
  TOP w0.076: U1.AF25 29.25,22.96 29.25,22.58 29.38,22.45
  TOP w0.104: v1(33.48,20.12) 33.48,21.23 32.42,22.29 31.21,22.29 30.76,21.84 30.1,21.84 29.5,22.45 29.38,22.45
  L3_IN1 w0.081: v1(44.05,23.15) 44.05,23.1 43.87,22.92 38.57,22.92 37.48,21.82 35.76,21.82 34.64,20.7 34.64,20.1 34.42,19.89 33.69,19.89 33.5,20.08 33.5,20.09 v1(33.48,20.12)
  BOTTOM w0.104: J7.15 44.99,25.1 44.07,24.18 44.07,23.17 v1(44.05,23.15)
ENET_TX_CTL: length 22.4
  TOP w0.076: U1.AF24 28.75,22.96 28.75,22.26 29.13,21.88 29.36,21.88
  TOP w0.104: v1(35.21,19.74) 34.97,19.5 31.4,19.5 30.2,20.7 30.2,21.22 29.54,21.88 29.36,21.88
  L3_IN1 w0.081: v1(46.69,21.9) 46.52,22.06 39.17,22.06 37.79,20.68 36.88,20.68 36.31,20.1 35.57,20.1 v1(35.21,19.74)
  BOTTOM w0.104: J7.1 46.21,22.3 46.61,21.9 v1(46.69,21.9)
ENET_TXC: length 23
  TOP w0.076: 28.48,21.02 28.48,22.7 U1.AG24
  TOP w0.104: v1(36.63,19.68) 36.2,19.25 29.92,19.25 29.52,19.65 29.29,19.88 29.29,19.88 28.48,20.69 28.48,21.02
  L3_IN1 w0.081: v1(44.87,21.23) 44.48,21.62 39.52,21.62 37.59,19.68 v1(36.63,19.68)
  BOTTOM w0.104: J7.5 45.23,23.1 44.87,22.73 v1(44.87,21.23)
GPIO1_IO01: length 28.7
  TOP w0.076: U1.AF14 23.74,22.96 23.74,21.02
  TOP w0.104: v1(34.65,5.22) 34.65,6.14 37.69,9.18 37.69,11.23 32.48,16.44 27.68,16.44 23.74,20.37 23.74,21.02
  BOTTOM w0.104: v1(34.65,5.22) 34.45,5.41 J5.64
GPIO1_IO05: length 32.5
  TOP w0.076: U1.AF12 22.74,22.96 22.74,22.52
  TOP w0.104: v1(34.47,4.59) 34.26,4.8 34.26,6.2 37.46,9.39 37.46,10.96 32.43,15.98 24.37,15.98 23.74,16.61 23.74,17.66 22.74,18.66 22.74,22.52
  BOTTOM w0.104: J5.62 34.05,5.02 v1(34.47,4.59)
GPIO1_IO06: length 31.4
  TOP w0.104: v1(33.57,4.64) 33.57,4.69 33.26,5 33.26,6.38 36.43,9.55 36.43,11.01 34.83,12.61 32.33,15.11 24.59,15.11 21.99,17.71 U1.AG11
  BOTTOM w0.104: v1(33.57,4.64) 33.25,4.96 J5.58
GPIO1_IO07: length 33.9
  TOP w0.076: U1.AF11 22.25,22.96 22.25,22.47
  TOP w0.104: 22.25,22.47 22.25,17.78 24.44,15.59 32.33,15.59 37.23,10.69 37.23,9.55 34.03,6.36 34.03,4.56 33.73,4.26 33.41,4.26 33.19,4.48 33.19,4.71 32.8,5.1 v1(32.57,5.1)
  BOTTOM w0.104: v1(32.57,5.1) 32.85,5.38 J5.56
GPIO1_IO08: length 32.6
  TOP w0.104: v1(32.78,4.58) 32.34,4.14 31.9,4.14 31.63,4.41 31.63,4.8 31.42,5.01 31.42,6.15 34.75,9.48 34.75,11.18 31.68,14.26 24.79,14.26 21.49,17.55 U1.AG10
  BOTTOM w0.104: J5.54 32.45,5.52 32.19,5.26 32.19,4.93 32.54,4.58 v1(32.78,4.58)
GPIO1_IO09: length 30.4
  TOP w0.076: 21.74,22.5 21.74,22.96 U1.AF10
  TOP w0.104: v1(31.81,5.17) 31.81,6.03 35.65,9.87 35.65,10.7 31.67,14.69 24.68,14.69 21.74,17.63 21.74,22.5
  BOTTOM w0.104: J5.52 32.05,5.62 31.81,5.37 v1(31.81,5.17)
GPIO1_IO10: length 28.1
  TOP w0.076: v1(21.97,24.15) 21.9,24.21 U1.AD10
  L3_IN1 w0.081: v1(21.97,24.15) 21.91,24.09 21.91,23.29 22.03,23.16 34.49,10.71 34.49,9.47 32.2,7.18 32.2,4.75 v1(32.02,4.57)
  BOTTOM w0.104: v1(32.02,4.57) 31.86,4.57 31.42,5.01 31.42,5.33 31.65,5.55 J5.50
GPIO1_IO11: length 29
  TOP w0.076: v1(21.98,24.7) 21.97,24.71 U1.AC10
  L3_IN1 w0.081: v1(31.25,4.62) 31.43,4.8 31.43,6.85 34.28,9.7 34.28,10.62 21.62,23.28 21.62,24.34 v1(21.98,24.7)
  BOTTOM w0.104: J5.46 30.85,5.48 30.66,5.29 30.66,4.96 31,4.62 v1(31.25,4.62)
GPIO1_IO12: length 27.4
  TOP w0.076: U1.AB10 21.95,25.21 v1(21.98,25.25)
  L3_IN1 w0.081: v1(21.98,25.25) 21.46,24.72 21.46,23.15 32.82,11.78 32.82,9.99 32.77,9.94 32.77,8.56 30.28,6.06 v1(30.28,5.17)
  BOTTOM w0.104: J5.44 30.45,5.41 30.28,5.23 v1(30.28,5.17)
GPIO1_IO13: length 28.9
  TOP w0.076: v1(20.54,24.16) 20.58,24.21 U1.AD9
  L3_IN1 w0.081: v1(30.45,4.62) 30.08,4.24 29.5,4.24 29.14,4.6 29.14,5.84 31.55,8.24 31.55,12.17 20.67,23.05 20.67,24.03 v1(20.54,24.16)
  BOTTOM w0.104: J5.42 30.05,5.49 29.9,5.34 29.9,5.01 30.29,4.62 v1(30.45,4.62)
GPIO1_IO14: length 26.4
  TOP w0.076: U1.AC9 20.55,24.71 v1(20.53,24.73)
  L3_IN1 w0.081: v1(20.53,24.73) 20.92,24.34 20.92,23.1 31.76,12.26 31.76,10.29 31.76,8.16 29.51,5.91 v1(29.51,5.17)
  BOTTOM w0.104: v1(29.51,5.17) 29.65,5.31 J5.40
GPIO1_IO15: length 28.5
  TOP w0.076: v1(20.54,25.28) 20.61,25.21 U1.AB9
  L3_IN1 w0.081: v1(20.54,25.28) 21.13,24.69 21.13,23.18 31.96,12.35 31.96,10.38 31.96,10.2 31.96,8.07 29.9,6.01 29.9,4.87 v1(29.65,4.62)
  BOTTOM w0.104: v1(29.65,4.62) 29.52,4.62 29.13,5.01 29.13,5.34 29.25,5.46 J5.38
I2C1_SCL: length 81
  TOP w0.076: U1.E9 20.57,33.71 v1(20.56,33.72)
  TOP w0.104: R10.2 18.01,47.47 18.01,48.24 v1(18.06,48.29) ; v2(1.58,20.7) 13.49,20.7 14.63,19.55 17.33,19.55 18.54,18.35 18.54,17.55 R48.1
  L3_IN1 w0.081: v1(20.56,33.72) 20.97,34.13 20.97,35.53 21.58,36.13 21.58,39.55 18.54,42.59 15.93,42.59 14.46,44.06 14.46,46.16 15.7,47.39 17.19,47.39 18.06,48.26 v1(18.06,48.29)
  BOTTOM w0.104: v1(18.06,48.29) 17.65,47.88 12.3,47.88 0.64,36.22 0.64,21.64 v2(1.58,20.7)
I2C1_SDA: length 74.3
  TOP w0.076: U1.F9 20.57,33.21 v1(20.52,33.16)
  TOP w0.104: v2(2.16,20.27) 2.36,20.47 13.4,20.47 14.54,19.32 16.93,19.32 18.13,18.12 R54.1 ; v1(18.39,47.85) 18.41,47.85 R11.2
  L3_IN1 w0.081: v1(18.39,47.85) 17.75,47.22 17.75,43.9 21.85,39.8 21.85,35.94 21.21,35.31 21.21,33.83 20.54,33.16 v1(20.52,33.16)
  BOTTOM w0.104: v2(2.16,20.27) 2.16,20.75 0.87,22.04 0.87,36.02 12.5,47.65 18.19,47.65 v1(18.39,47.85)
I2C2_SCL: length 23.9
  TOP w0.076: v1(21.94,34.3) 21.84,34.21 U1.D10
  TOP w0.104: R12.2 16.23,47.86 16.84,47.86 v1(17.28,48.29)
  L3_IN1 w0.081: v1(21.94,34.3) 21.93,34.3 21.85,34.38 21.85,34.99 22.63,35.77 22.63,40.39 19.07,43.95 19.07,46.81 19.5,47.24 19.5,48.49 18.79,49.2 17.11,49.2 16.86,48.95 16.86,48.71 v1(17.28,48.29)
  BOTTOM w0.104: J4.22 17.67,48.66 17.3,48.29 v1(17.28,48.29)
I2C2_SDA: length 24.9
  TOP w0.076: U1.D9 20.93,34.27 v1(20.53,34.27)
  TOP w0.104: v1(18.06,48.83) 18.05,48.83 17.66,48.43 17.66,48.13 16.84,47.32 R13.2
  L3_IN1 w0.081: v1(18.06,48.83) 18.06,48.82 17.65,48.41 17.65,48.14 17.11,47.6 15.61,47.6 14.23,46.22 14.23,44 15.99,42.24 18.33,42.24 21.33,39.24 21.33,36.31 20.63,35.62 20.63,34.37 v1(20.53,34.27)
  BOTTOM w0.104: v1(18.06,48.83) 18.07,48.83 J4.24
I2C3_SCL: length 20
  TOP w0.076: U1.E10 21.96,33.71 v1(21.97,33.72)
  TOP w0.104: v1(19.13,47.98) 19.13,47.73 19.54,47.32 R14.2
  L3_IN1 w0.081: v1(19.13,47.98) 19.13,47.4 18.79,47.07 18.79,43.72 22.33,40.19 22.33,35.73 21.59,34.99 21.59,34.09 v1(21.97,33.72)
  BOTTOM w0.104: J4.26 18.47,48.46 18.94,47.98 v1(19.13,47.98)
I2C3_SDA: length 22.1
  TOP w0.076: U1.F10 21.89,33.21 v1(21.96,33.14)
  TOP w0.104: v1(18.87,48.6) 19.06,48.6 19.8,47.86 20.07,47.86 20.6,47.32 R15.2
  L3_IN1 w0.081: v1(21.96,33.14) 21.41,33.68 21.41,35.07 22.06,35.72 22.06,40.03 17.98,44.11 17.98,46.92 18.76,47.7 18.76,48.49 v1(18.87,48.6)
  BOTTOM w0.104: v1(18.87,48.6) J4.28
I2C4_SCL: length 20.1
  TOP w0.076: v1(22.5,34.3) 22.59,34.21 U1.D13
  TOP w0.104: R16.2 21.77,47.32 21.23,47.86 20.47,47.86 20.09,48.24 v1(19.98,48.24)
  L3_IN1 w0.081: v1(19.98,48.24) 20.06,48.15 20.06,43.53 22.87,40.72 22.87,34.68 v1(22.5,34.3)
  BOTTOM w0.104: v1(19.98,48.24) 19.65,48.24 19.27,48.62 J4.30
I2C4_SDA: length 21.4
  TOP w0.076: U1.E13 22.56,33.71 v1(22.54,33.73)
  TOP w0.104: v1(20.22,48.71) 20.22,48.58 20.72,48.09 21.45,48.09 21.75,47.8 22.3,47.8 22.78,47.32 R17.2
  L3_IN1 w0.081: v1(20.22,48.71) 20.35,48.58 20.35,43.92 23.13,41.15 23.13,34.3 22.56,33.73 v1(22.54,33.73)
  BOTTOM w0.104: J4.34 20.07,48.97 20.22,48.81 v1(20.22,48.71)
JTAG_MOD: length 2.6
  TOP w0.114: U1.D27 30.07,34.29 30.38,34.29 31.12,35.02 v1(31.69,35.02)
  BOTTOM w0.104: v1(31.69,35.02) 31.29,35.02 R23.1
JTAG_TCK: length 28.4
  TOP w0.076: 30.37,33.46 29.75,33.46 U1.F26
  TOP w0.104: 33.2,33.75 30.66,33.75 30.37,33.46
  TOP w0.114: 33.2,33.75 33.21,33.76 33.98,33.76 v1(34.03,33.8) 34.06,33.83 34.98,33.83 TP4.1
  L3_IN1 w0.081: v1(25.76,48.41) 25.88,48.41 27.2,47.09 27.21,47.09 27.63,46.67 30.67,46.67 33.85,43.49 33.85,35.36 34.24,34.98 34.24,34.02 v1(34.03,33.8)
  BOTTOM w0.104: R18.1 34.03,33.97 v1(34.03,33.8) ; v1(25.76,48.41) 25.67,48.5 J4.62
JTAG_TDI: length 26.2
  TOP w0.104: U1.E27 30.36,33.71 30.84,34.19 32.1,34.19 32.31,33.98 33.09,33.98
  TOP w0.114: TP2.1 33.59,34.37 33.38,34.15 v1(33.28,34.15) 33.26,34.15 33.09,33.98
  L3_IN1 w0.081: v1(25.28,47.78) 25.3,47.77 25.3,47.65 26.49,46.46 26.95,46.46 27.31,46.11 27.31,45.51 29.17,43.65 32.3,43.65 33.23,42.72 33.23,34.21 33.28,34.15 v1(33.28,34.15)
  BOTTOM w0.104: J4.54 24.07,48.58 24.77,47.88 25.19,47.88 v1(25.28,47.78)
JTAG_TDO: length 25.2
  TOP w0.076: U1.E26 29.75,33.96 30.33,33.96 30.7,34.33
  TOP w0.114: TP5.1 32.59,34.59 v1(32.02,34.59) 30.96,34.59 30.7,34.33
  L3_IN1 w0.081: v1(32.02,34.59) 32.17,34.59 33.02,35.44 33.02,42.64 32.21,43.44 28.67,43.44 26.29,45.82 26.29,46.18 24.98,47.48 v1(24.78,47.48)
  BOTTOM w0.104: J4.52 23.67,48.65 24.78,47.54 v1(24.78,47.48)
JTAG_TMS: length 24.2
  TOP w0.114: TP3.1 33.77,33.36 v1(33.23,33.36)
  L3_IN1 w0.081: v1(33.23,33.36) 33.66,33.78 33.66,34.3 33.43,34.52 33.43,42.81 32.39,43.86 29.37,43.86 27.56,45.67 27.56,46.15 27.04,46.67 26.57,46.67 25.65,47.59 25.65,47.94 25.14,48.45 v1(24.93,48.45)
  BOTTOM w0.104: R27.2 32.26,33.36 v1(33.23,33.36) ; v1(24.93,48.45) 24.87,48.51 J4.58
JTAG_TMS_R: length 1.6
  TOP w0.104: v1(30.96,33.36) 30.81,33.21 U1.F27
  BOTTOM w0.104: v1(30.96,33.36) 30.97,33.35 R27.1
M.2_32K_OUT: length 1.9
  TOP w0.104: v1(28.74,8.1) 28.93,8.1 R116.2
  BOTTOM w0.104: J5.37 29.25,8.61 v1(28.74,8.1)
NVCC_1V8: length 115
  TOP w0.203: v2(5.74,7.82) 5.81,7.82 6.14,8.14 U8.14 ; R106.1 v1(18.67,4.29)
  TOP w0.254: U1.J11 U1.J12 ; U1.J12 U1.J13 ; U1.J12 v1(22.49,32.22) ; v1(3.79,26.64) 3.82,26.64 U2.T4 ; U1.T19 U1.U19 ; U1.U19 26.41,27.71 v1(26.46,27.67) 26.49,27.63 U1.V20 ; U1.U19 U1.V19 ; v1(43.68,31.84) 43.54,31.98 U4.P5 ; U1.W12 22.49,26.26 v1(22.5,26.26) ; v1(3.76,32.46) 4.08,32.13 U2.G4 ; U4.N4 U4.P3 42.54,32.09 42.41,31.97 v1(42.41,31.8) ; v1(2.16,25.32) 2.09,25.32 U2.U1 ; v1(44.25,37.42) 44.23,37.44 44.23,37.65 U4.C6 ; v1(26.46,30.72) 26.45,30.71 U1.L19 U1.M19 ; v1(11.17,25.59) 10.63,25.59 U2.U12 ; R197.1 v1(16.83,6.11) 17.08,5.85 R196.1 ; U7.A1 55.65,43.18 ; U2.F1 v1(2.12,32.45) ; v1(8.56,25.98) 8.48,25.98 U2.T9 ; U1.AB13 22.6,25.21 v1(22.54,25.26) ; U4.M4 43.04,33.76 v1(42.99,33.81) ; v1(7.78,32.46) 7.86,32.46 U2.G9 ; U2.F12 v1(11.08,32.78)
  TOP w0.305: R12.1 R13.1 R10.1 R11.1 R14.1 R15.1 R16.1 R17.1 28.15,46.78 28.63,46.31 28.63,45.59 v2(29.11,45.11) ; v1(38.85,34.11) 38.6,33.85 R117.1 ; R118.1 38.88,29.5 v1(39.61,30.23)
  TOP w0.381: 55.65,43.18 54.85,43.18 C146.1 54.82,43.64 54.2,44.26 v1(49.76,44.26) ; v1(45.85,26.36) 44.6,26.36 41.64,23.4 v1(37.05,23.4)
  L3_IN1 w0.254: v1(22.5,26.26) 22.64,26.11 22.64,25.36 v1(22.54,25.26) 22.55,25.26 23.2,25.26 23.99,26.05 23.99,26.43 24.29,26.73 25.52,26.73 v1(26.46,27.67) 26.46,28.54 26.97,29.05 26.97,29.79 26.5,30.27 26.5,30.68 v1(26.46,30.72)
  L5_PWR_2 w0.254: v1(22.49,32.22) 22.49,32.19 22.94,31.74 25.58,31.74 26.46,30.86 v1(26.46,30.72) ; v1(3.76,32.46) 4.11,32.1 5.97,32.1 6.4,32.54 7.7,32.54 v1(7.78,32.46) 8,32.46 8.79,33.25 10.62,33.25 v1(11.08,32.78)
  BOTTOM w0.203: C5.1 22.86,32.59 v1(22.49,32.22) ; C21.1 23.28,23.55 C266.1
  BOTTOM w0.254: v1(43.68,31.84) 43.93,31.58 C132.1 ; C105.1 2.09,25.25 v1(2.16,25.32) ; v1(11.08,32.78) 11.15,32.85 C372.1 ; C370.1 8.6,26.02 v1(8.56,25.98) ; v1(3.79,26.64) 3.99,26.44 C109.1 ; v1(42.41,31.8) 42.33,31.72 C133.1 ; v1(2.12,32.45) 2.11,32.45 C108.1 ; C371.1 3.85,32.37 v1(3.76,32.46) ; C384.1 7.85,32.52 v1(7.78,32.46) ; v2(5.74,7.82) 5.12,7.82 R61.2 ; R77.2 v1(36.71,45.15) ; C23.1 26.09,27.3 v1(26.46,27.67) 26.8,27.33 C3.1 ; C241.1 26.46,30.72 v1(26.46,30.72) ; C21.1 23.3,23.75 23.04,24.01 23.04,24.85 22.62,25.26 22.55,25.26 v1(22.54,25.26) ; C131.1 44.28,37.45 v1(44.25,37.42) ; C106.1 11.18,25.58 v1(11.17,25.59)
  BOTTOM w0.381: v1(37.05,23.4) 37.05,29.65 R79.2 35.58,31.1 R47.2 32.59,31.1 R78.2 ; U5.8 47.7,44.26 C138.1 ; v1(18.67,4.29) 18.64,4.29 v1(16.83,6.11) ; v1(45.47,35.67) 46.47,36.67 48.46,36.67 49.73,37.94 49.73,39.4 49.46,39.67 R37.1 48.71,39.67 48.33,40.05 48.33,42.96 48.71,43.34 C139.1 49.01,44.25 C138.1 ; C138.1 v1(49.76,44.26) ; v1(42.99,33.81) 42.87,33.92 C130.1
  vias: v1(4.16,6.4) v1(4.16,5.56) v1(5.18,6.43) v1(5.15,5.61) v2(26.18,5.04) v2(26.18,4.4) v2(26.81,5.04) v2(26.81,4.4) v2(27.45,5.04) v2(27.45,4.4) v2(28.08,5.04) v2(28.08,4.4) v2(28.72,5.04) v2(28.72,4.4)
NVCC_3V3: length 53.4
  TOP w0.104: v2(4.37,7.9) 2.59,6.12 TP25.1
  TOP w0.254: U1.H10 21.92,32.21 v1(21.94,32.18) ; U4.K9 45.54,34.8 v1(45.49,34.85) ; v1(25,26.23) 24.99,26.24 U1.W17 ; v1(26.26,31.67) 26.25,31.67 25.99,31.41 U1.K19 ; v1(46.53,34.77) 46.46,34.84 U4.J10 ; R201.1 14.95,6.13 v2(14.73,5.92) 14.51,6.13 R200.1 ; v1(44.09,36.25) 44.09,36.35 44.04,36.41 U4.E6 ; v1(21.94,26.26) 21.9,26.21 U1.Y10 ; U4.F5 43.37,36.34 43.15,36.56 v1(43.07,36.56)
  TOP w0.305: R125.1 42.69,44.18 42.88,43.99 v1(42.88,43.78)
  TOP w0.381: R137.1 4.35,7.92 v2(4.37,7.9) ; v2(54.62,41.06) 54.62,41.06 R153.1
  TOP w0.508: U9.9 65.55,32.12 v2(66.07,31.59)
  L3_IN1 w0.254: v2(19.76,7.72) 20.24,7.24 v2(25.2,7.24)
  L3_IN1 w0.305: v1(42.88,43.78) 42.85,43.76 42.85,36.77 v1(43.07,36.56)
  BOTTOM w0.254: v1(25,26.23) 25.5,25.74 C6.1 25.5,25.35 25.2,25.05 C260.1 25.2,24.63 25.76,24.08 25.76,23.27 ; v1(21.94,32.18) 21.93,32.19 C8.1 ; v1(21.94,26.26) 21.69,26.01 C264.1 21.69,25.58 21.51,25.4 21.51,19.13 19.83,17.44 19.83,7.79 v2(19.76,7.72) ; v1(26.26,31.67) 26.28,31.67 26.49,31.88 C30.1 ; C129.1 44.09,36.26 v1(44.09,36.25) ; v1(43.07,36.56) 43.02,36.61 C128.1
  BOTTOM w0.381: v2(14.73,5.92) 13.89,5.08 v2(11.94,5.08)
  vias: v2(11.33,5.08) v2(11.38,4.24) v2(11.94,4.24) v2(26.82,10.53) v2(26.82,9.9) v2(28.09,10.53) v2(28.09,9.9) v2(28.72,10.53) v2(28.72,9.9)
NVCC_DRAM_1V1: length 46.6
  TOP w0.203: v2(9.01,15.13) U8.52
  TOP w0.254: v1(5.43,25.63) U2.U5 ; v1(5.43,24.33) U2.W5 ; v1(2.12,31.19) 2.06,31.24 2.02,31.24 U2.H1 ; U2.A9 8.4,35.81 v1(8.58,35.81) 8.98,35.41 U2.B10 ; U2.H8 7.29,31.39 v1(6.83,31.39) ; U2.N12 11.04,28.23 11.08,28.27 v1(11.1,28.27) ; U2.A4 3.86,35.71 v1(3.78,35.71) 3.71,35.71 U2.B3 ; U2.D5 5.43,34.08 v1(5.43,34.09) ; v1(9.38,25.31) 9.31,25.31 U2.U10 ; U2.B8 v1(6.88,35.38) ; v1(5.43,32.78) U2.F5 ; v1(8.66,27.92) U2.N10 ; v1(2.13,28.52) 2.07,28.52 U2.N1 ; v1(9.38,29.86) 9.31,29.86 U2.K10 ; U2.R8 v1(6.93,26.93) ; U2.AA3 3.71,22.71 v1(3.78,22.71) 3.86,22.71 U2.AB4 ; U2.R1 2.1,26.62 v1(2.1,26.62) ; v1(5.43,31.44) 5.39,31.48 U2.H5 ; U2.W12 v1(11.08,24.33) ; U2.D1 2.14,34.44 v1(2.14,34.46) ; U2.F3 3.15,32.55 v1(3,32.55) 2.58,32.14 U2.G2 ; U2.W8 v1(6.88,24.33) ; v1(6.93,34.19) 7.04,34.08 U2.D8 ; U1.P7 v1(19.53,29.21) ; v1(11.11,34.19) 11,34.08 U2.D12 ; U2.AA8 v1(6.93,23.03) ; v1(11.08,26.98) 11.04,26.93 U2.R12 ; U2.U3 v1(2.98,25.96) ; v1(7.79,33.22) 7.79,33.19 U2.F8 ; U2.U8 v1(6.88,25.63) ; v1(11.1,30.13) 11.04,30.18 U2.K12 ; U2.AA5 v1(5.43,23.03) ; U2.B5 v1(5.54,35.38) ; U2.AA10 8.66,22.72 v1(8.66,22.72) 8.55,22.61 8.41,22.61 U2.AB9 ; v1(2.18,24) 2.11,24 U2.W1 ; U1.V8 v1(20.49,27.64) ; v1(3.78,29.86) 3.71,29.86 U2.K3 ; v1(11.08,31.44) 11.04,31.48 U2.H12 ; U2.K1 v1(2.1,29.87) ; U1.N8 v1(20.49,30.16) ; U2.F10 v1(9.36,32.4)
  TOP w0.305: v1(3.78,28.56) 3.71,28.56 U2.N3 ; U2.R5 v1(5.43,26.93)
  BOTTOM w0.203: C379.1 11.13,31.48 v1(11.08,31.44)
  BOTTOM w0.254: v1(3.78,28.56) 3.71,28.49 C375.1 ; v1(20.51,28.26) 20.49,28.28 20.49,28.54 C93.1 ; v1(3.78,29.86) 3.88,29.96 C376.1 ; v2(9.01,15.13) 9.01,17.03 7.75,18.29 ; C373.1 11.13,30.16 v1(11.1,30.13) ; C91.1 19.2,28.78 19.53,29.11 v1(19.53,29.21) ; v1(5.43,31.44) 5.43,31.99 C112.1 ; C110.1 8.67,27.91 v1(8.66,27.92) ; v1(6.93,34.19) 7.34,33.78 C114.1 ; v1(11.08,26.98) 11.06,27.01 C113.1 ; v1(8.58,35.81) 8.67,35.9 C118.1 ; v1(11.1,28.27) 11.22,28.16 C378.1 ; v1(11.11,34.19) 10.87,33.95 C380.1 ; C115.1 2.06,29.82 v1(2.1,29.87) ; v1(20.49,29.24) 20.49,29.42 C92.1 20.49,29.99 v1(20.49,30.16) ; v1(2.18,24) 2.16,24.02 C119.1 ; v1(20.47,31.65) 20.19,31.65 C89.1 20.37,30.87 20.37,30.84 v1(20.49,30.71) ; v1(6.93,26.93) 7.06,26.81 C382.1 ; v1(9.38,25.31) 9.53,25.16 C111.1 ; v1(6.88,35.38) 6.85,35.42 R157.1 ; C117.1 2.05,34.54 v1(2.14,34.46) ; C94.1 21.03,32.42 v1(21.03,31.85) 20.91,31.74 C95.1 ; C381.1 2.02,28.41 v1(2.13,28.52) ; C374.1 11.09,24.34 v1(11.08,24.33)
  BOTTOM w0.305: v1(20.49,29.24) 20.65,29.08 C90.1 ; R5.1 5.5,35.42 v1(5.54,35.38)
  vias: v1(5.31,19.56) v1(5.31,18.9) v1(6.09,19.56) v1(6.09,18.9) v1(6.82,19.55) v1(6.82,18.89) v1(20.43,26.78)
NVCC_ENET: length 21.5
  TOP w0.254: U1.W22 27.49,26.33 v1(27.42,26.25)
  L3_IN1 w0.254: v1(34.7,23.98) 34.86,23.98 34.94,24.06 35.94,24.06 37.41,25.53 v1(44.7,25.53)
  BOTTOM w0.203: v1(44.7,25.53) 44.7,25.72 44.91,25.93 45.7,25.93 45.73,25.9 J7.19
  BOTTOM w0.254: 27.54,24.74 27.54,23.88 C2.1 27.87,23.86 28.06,23.66 28.06,23.5 28.35,23.22 33.91,23.22 34.67,23.98 34.7,23.98 v1(34.7,23.98)
NVCC_SD2: length 47.7
  TOP w0.203: TP33.1 4.74,15.43 6.62,15.43 v2(7.11,14.94) 7.53,14.94 7.81,14.66 U8.55
  TOP w0.254: v1(27.46,27.69) 27.49,27.66 U1.V22
  L5_PWR_2 w0.381: v1(27.46,27.69) 27.46,27.53 27.81,27.19 29.72,27.19 30.1,26.81 30.1,24.22 27.74,21.86 27.74,18.34 24.89,15.49 20.95,15.49 19.51,16.94 8.41,16.94 7.08,15.61 7.08,14.96 v2(7.11,14.94)
  BOTTOM w0.254: R133.1 R119.1 31.4,26.46 R120.1 29.49,26.72 28.38,26.72 27.87,27.23 C17.1 27.46,27.46 v1(27.46,27.69) ; C365.1 7.26,14.78 v2(7.11,14.94)
NVCC_SNVS_1V8: length 89.5
  TOP w0.203: U8.3 5.84,12.54 v2(5.73,12.65) 5.53,12.65 5.25,12.93 5.24,12.93 4.55,13.61 2.8,13.61 TP28.1
  TOP w0.254: v1(35.49,41.08) 33.32,41.08 32.79,40.54 R21.1 32.57,41.65 R20.1 ; U1.J22 27.49,32.16 v1(27.49,32.16) ; v1(39.67,44.22) R102.1
  L3_IN1 w0.254: v1(39.67,44.22) 38.63,44.22 v1(35.49,41.08)
  L5_PWR_2 w0.254: v1(35.49,41.08) 35.47,41.1 28.9,41.1 27.07,39.27 27.07,37.62 29.57,35.13 29.57,32.08 29.21,31.73 27.71,31.73 27.49,31.95 v1(27.49,32.16)
  L5_PWR_2 w0.381: v1(35.49,41.08) 35.49,38.08 32.7,35.3 32.7,30.98 33.11,30.57 33.11,20.54 25.89,13.31 6.39,13.31 v2(5.73,12.65)
  BOTTOM w0.254: C391.1 27.49,31.81 v1(27.49,32.16) ; v2(5.73,12.65) 5.73,12.58 6.34,11.97 C333.1
